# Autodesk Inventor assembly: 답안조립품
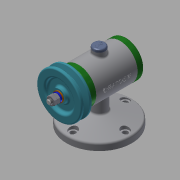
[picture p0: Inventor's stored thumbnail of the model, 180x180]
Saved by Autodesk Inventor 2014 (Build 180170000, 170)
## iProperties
Created: 2018-12
Part Number: 답안조립품
Document SubType Name: Assembly
Designer: kh
Author: kh
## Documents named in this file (15)
- C:\Users\kh\Desktop\481207V1014\답안조립품.iam
- C:\Users\kh\Desktop\481207V1014\본체.ipt
- C:\Users\kh\Desktop\481207V1014\V벨트풀리.ipt
- C:\Users\kh\Desktop\481207V1014\고무캡.ipt
- C:\Users\kh\Desktop\481207V1014\너트 M8.ipt
- 너트 M8.ipt
- C:\Users\kh\Desktop\481207V1014\뒤커버.ipt
- C:\Users\kh\Desktop\481207V1014\베어링 15 x 32 x 9.ipt
- C:\Users\kh\Desktop\481207V1014\볼트 M4 x 12.ipt
- C:\Users\kh\Desktop\481207V1014\스프링와셔 8.ipt
- C:\Users\kh\Desktop\481207V1014\앞커버.ipt
- C:\Users\kh\Desktop\481207V1014\오일 실 15 25 7.ipt
- C:\Users\kh\Desktop\481207V1014\와셔 8x17.ipt
- C:\Users\kh\Desktop\481207V1014\축.ipt
- C:\Users\kh\Desktop\481207V1014\키 3 x 3 x 12.ipt
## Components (2 placed, 2 different names)
1. V벨트풀리:1 — Insert:14, Mate:1, Insert:15
2. 고무캡:1 — Insert:13
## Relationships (4: Insert 3, Mate 1)
- Insert:13: 고무캡:1
- Insert:14: V벨트풀리:1
- Mate:1: V벨트풀리:1
- Insert:15: V벨트풀리:1
